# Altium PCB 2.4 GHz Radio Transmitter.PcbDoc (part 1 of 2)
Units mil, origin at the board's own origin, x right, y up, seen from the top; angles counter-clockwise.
Board outline 5905.26 x 4050.27 mil, 4 copper layers (Top Layer, GND, Power, Bottom Layer), stack 63.355 mil thick; 215 components, 108 nets, 659 pads, 107 vias.
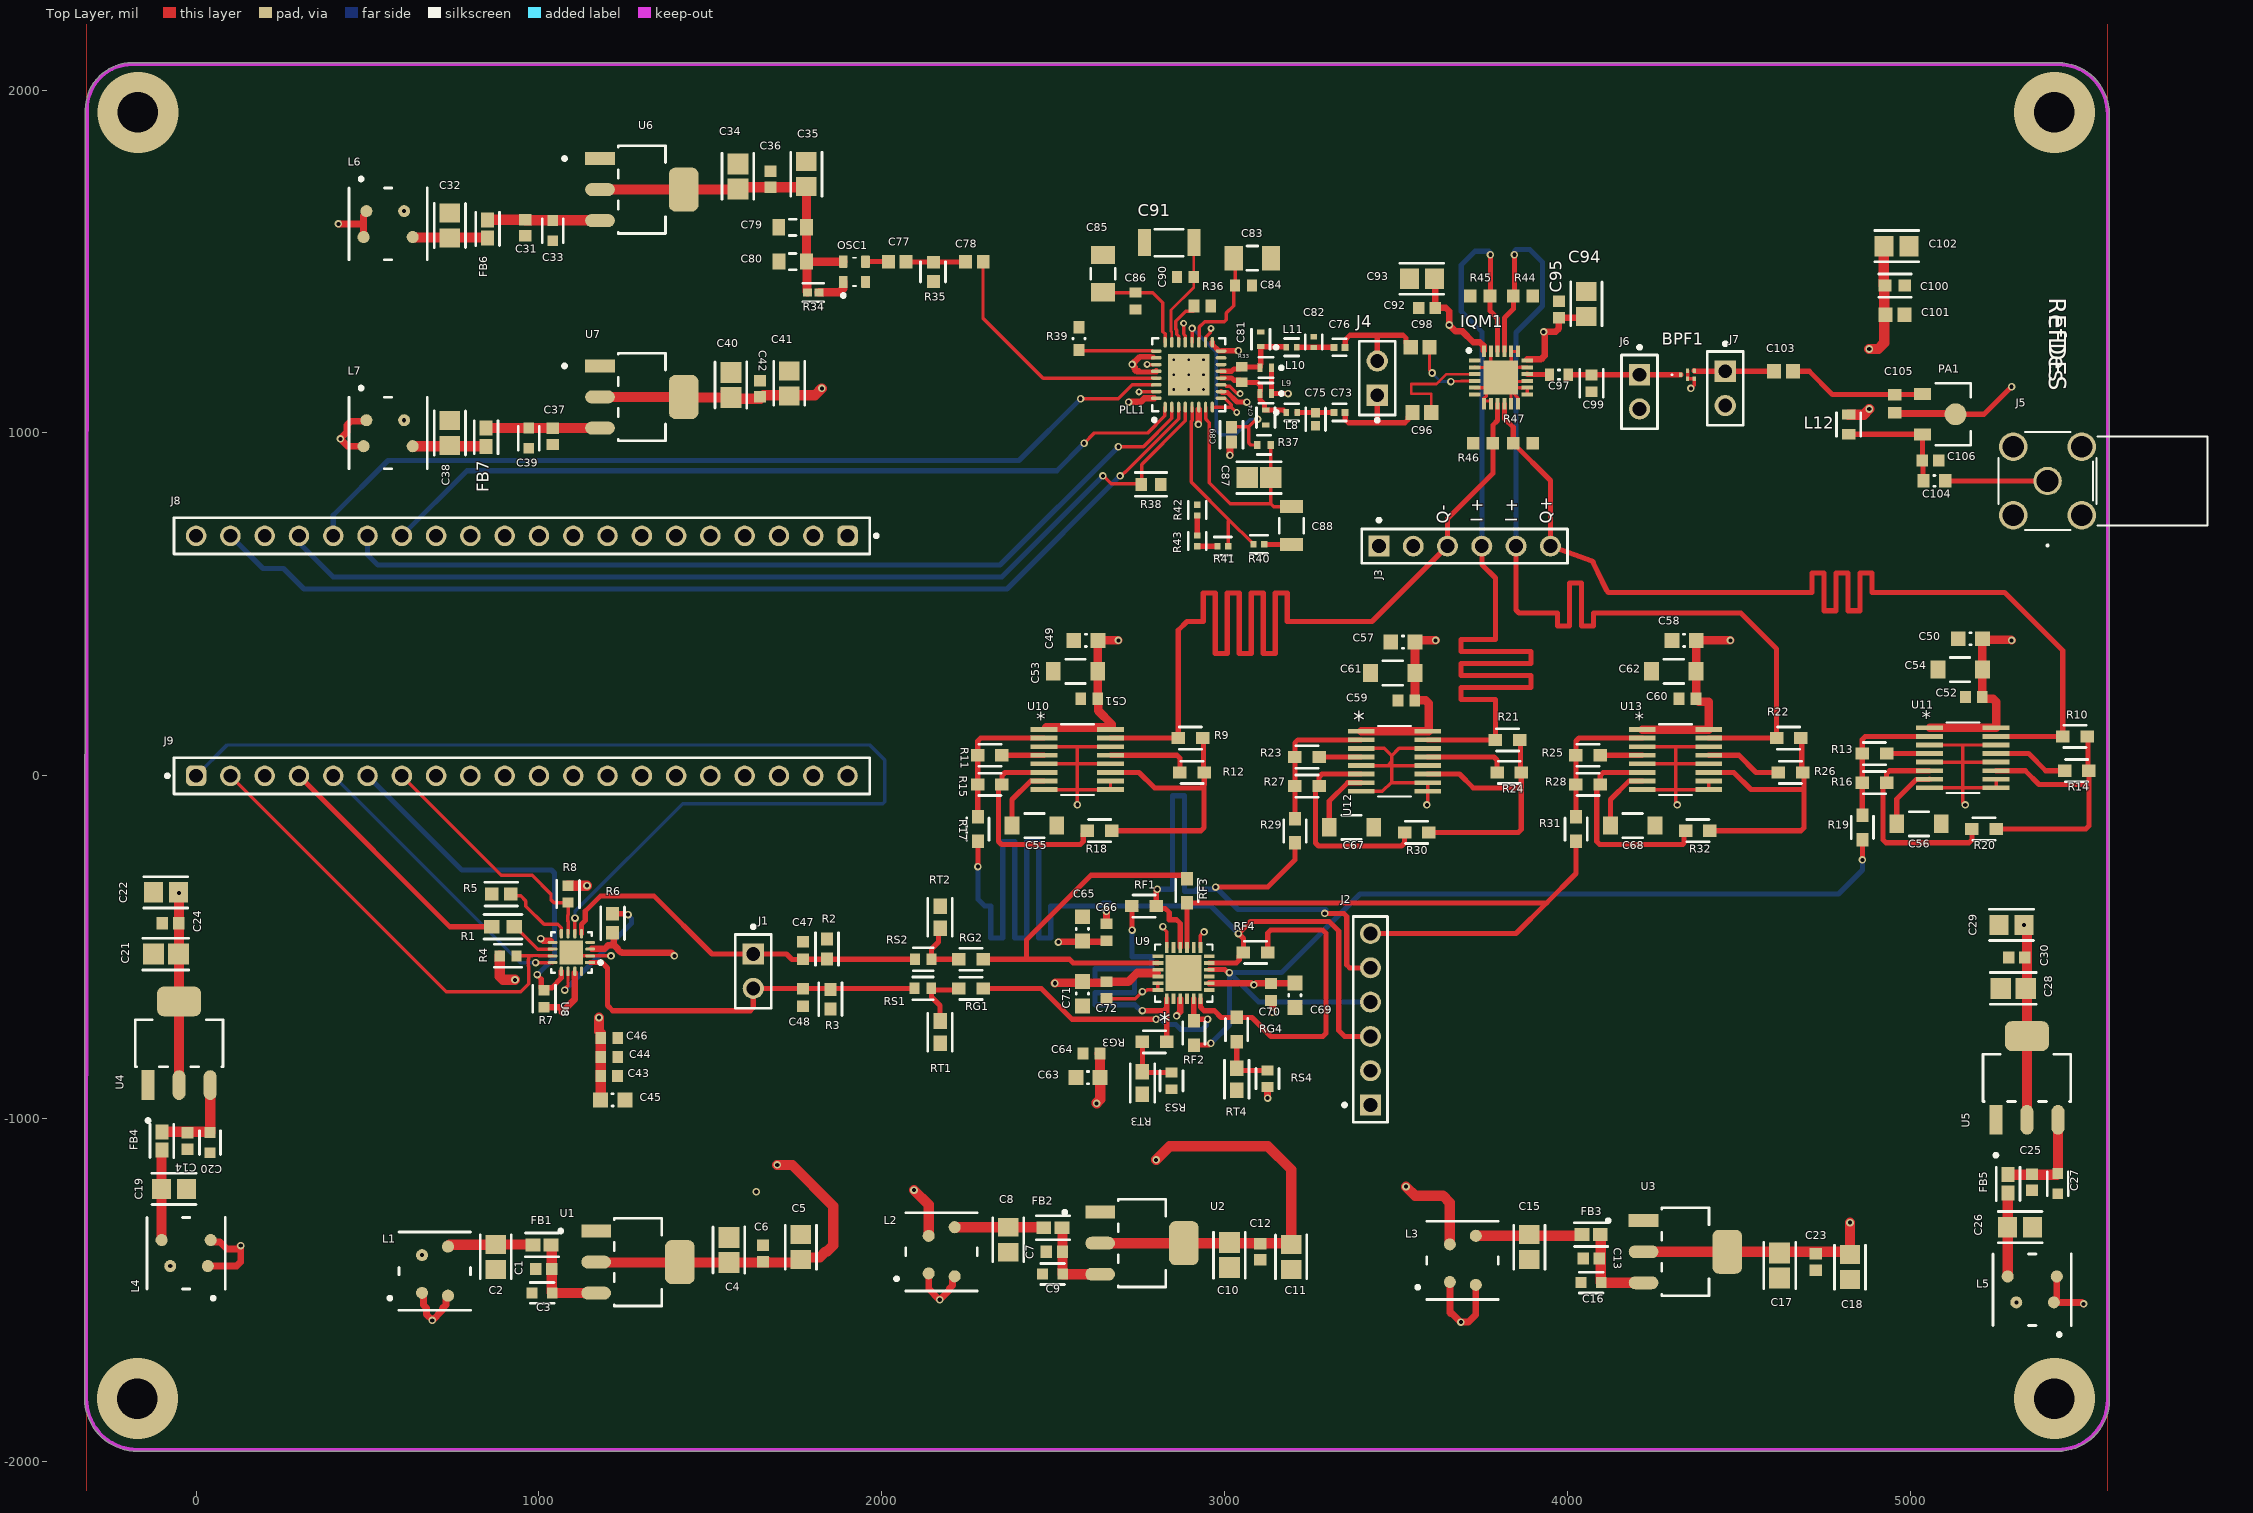
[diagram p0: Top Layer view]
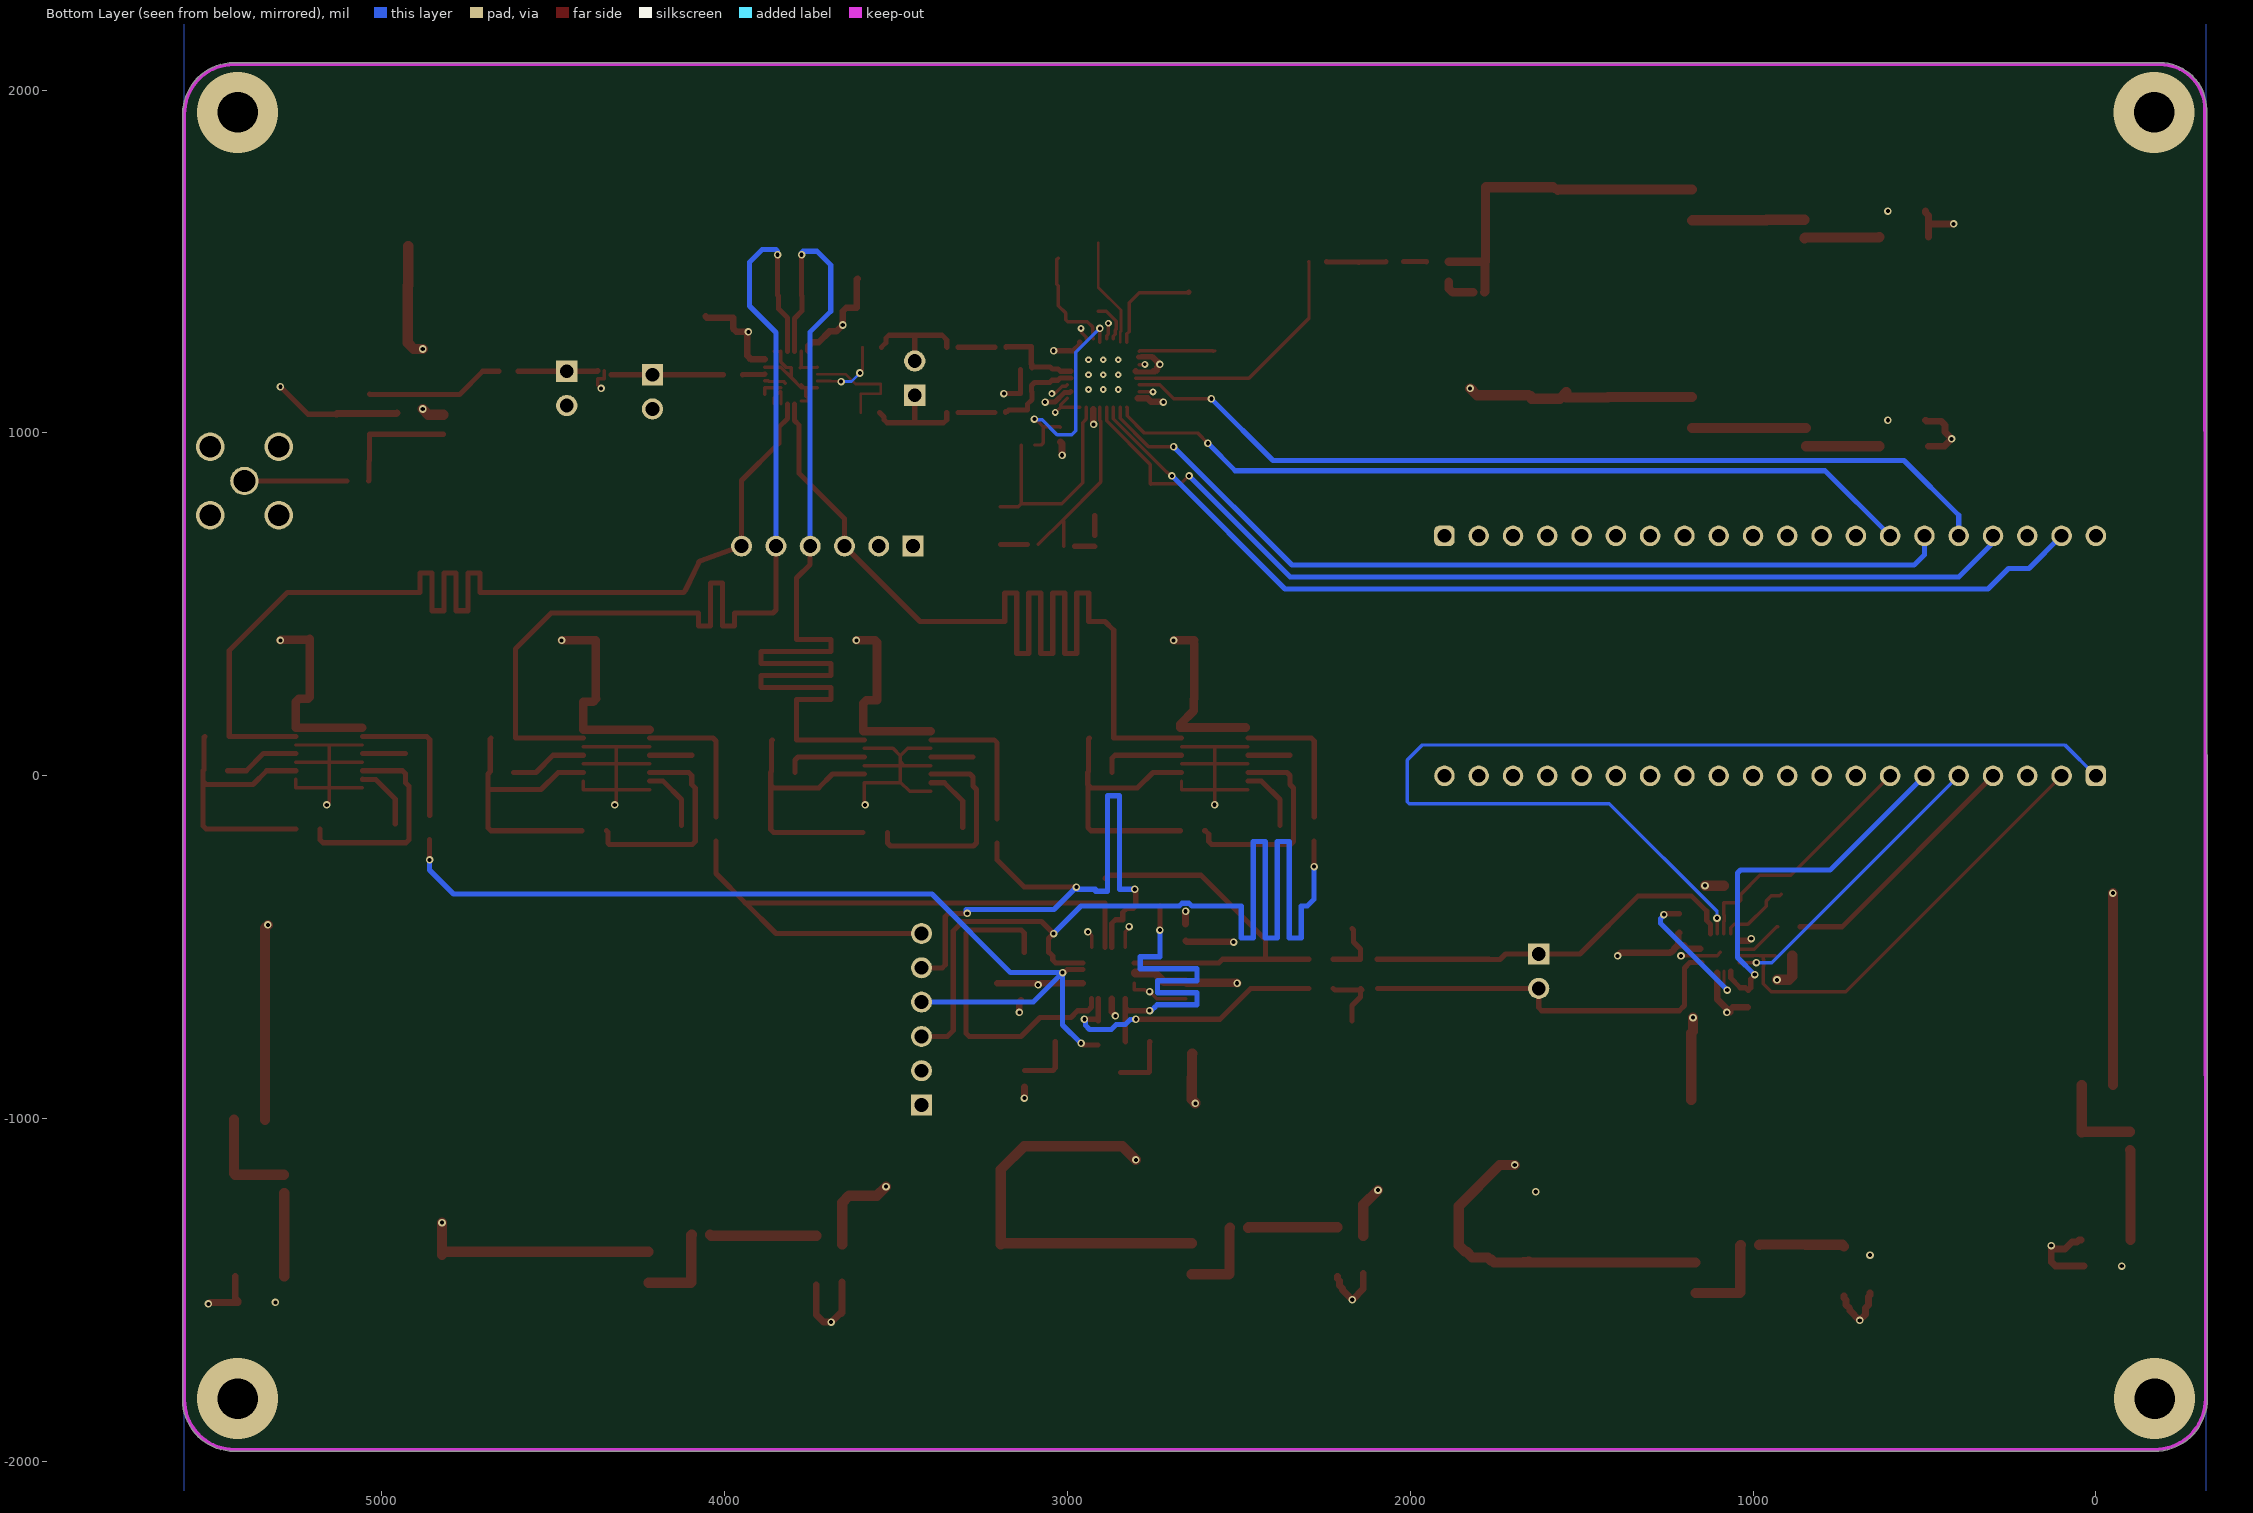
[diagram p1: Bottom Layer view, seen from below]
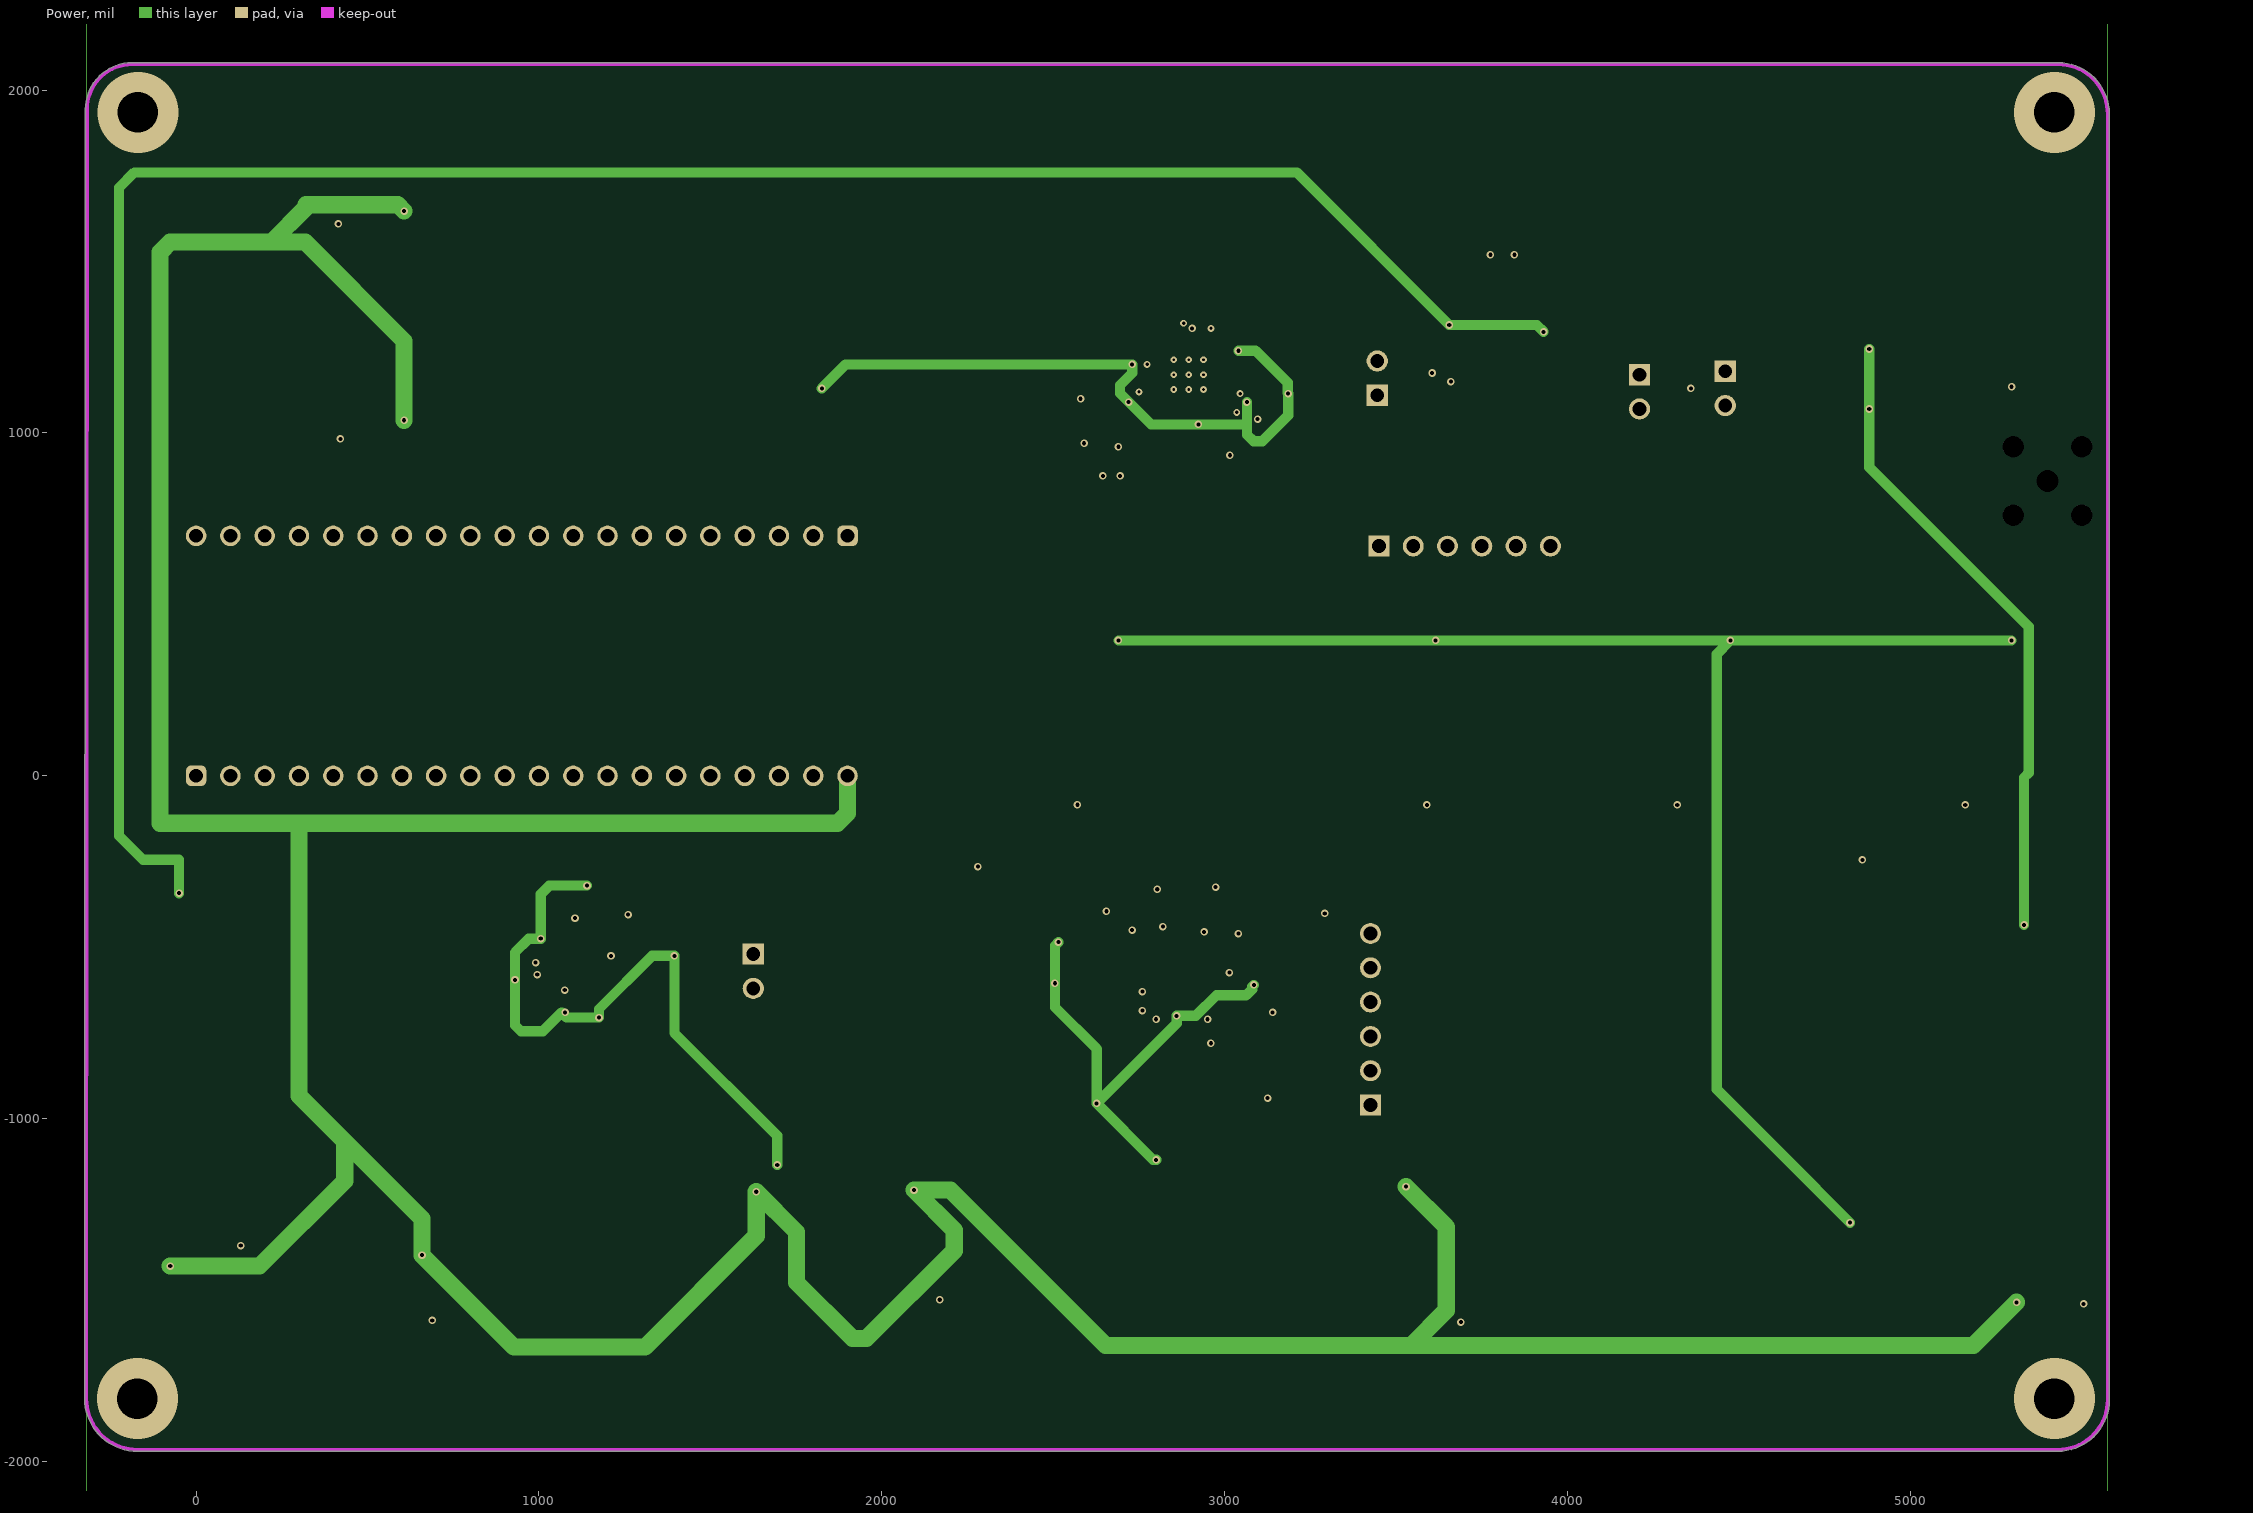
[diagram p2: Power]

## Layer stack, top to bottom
Top Solder: solder mask 1, Solder Resist, Dk 3.6
Top Layer: signal copper 1.378
Dielectric 1: prepreg 7.957, FR-4, Dk 3.61
GND: signal copper 1.378
Core: core 41.929, FR-4, Dk 4.4
Power: signal copper 1.378
Dielectric 2: prepreg 7.957, FR-4, Dk 3.61
Bottom Layer: signal copper 1.378
Bottom Solder: solder mask 1, Solder Resist, Dk 3.6

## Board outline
-325.02,-1816.32 -322.69,1944.12 cw(c-186.81,1944.11) -186.81,2080 5431.44,2080.02 5431.46,2080.01 cw(c5430.72,1930.72) 5580.02,1930.72 5580.04,1930 5580.25,-1819.6 cw(c5429.83,-1819.6) 5429.83,-1970.01 -171.08,-1970.26 cw(c-171.08,-1816.32)

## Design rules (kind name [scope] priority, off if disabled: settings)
AssemblyTestPointUsage [All] p0: scope1count=1 scope1_0_kind=Board scope1_0_value=Board scope2count=1 scope2_0_kind=Board scope2_0_value=Board commentlength=0
AssemblyTestpoint [All] p0: scope1count=1 scope1_0_kind=Board scope1_0_value=Board scope2count=1 scope2_0_kind=Board scope2_0_value=Board commentlength=0
BoardOutlineClearance [All] p0: scope1count=1 scope1_0_kind=Board scope1_0_value=Board scope2count=1 scope2_0_kind=Board scope2_0_value=Board commentlength=0 gap=15
BoardOutlineClearance [All] p1: gap=15 ignorepadtopadclearanceinfootprint=FALSE
Clearance [All] p0: scope1count=1 scope1_0_kind=Board scope1_0_value=Board scope2count=1 scope2_0_kind=Board scope2_0_value=Board commentlength=0 gap=5
Clearance "Clearance Polygons" [All] p0 off: scope1count=1 scope1_0_kind=Board scope1_0_value=Board scope2count=1 scope2_0_kind=Board scope2_0_value=Board commentlength=48 gap=10 // Protel DXP Scope 1 Expression Was: InPolygon
Clearance "Clearance Polygons" [InPolygon] p1: gap=10 ignorepadtopadclearanceinfootprint=FALSE
Clearance [All] p2: gap=5 ignorepadtopadclearanceinfootprint=FALSE
ComponentClearance [All] p0: scope1count=1 scope1_0_kind=Board scope1_0_value=Board scope2count=1 scope2_0_kind=Board scope2_0_value=Board commentlength=0 gap=1 collisioncheckmode=3
ComponentClearance "HM-TRP & UFL" [All] p0: scope1count=1 scope1_0_kind=Component scope1_0_value=X1 scope2count=1 scope2_0_kind=Component scope2_0_value=U1 commentlength=0 gap=0 collisioncheckmode=3
ComponentClearance "HM-TRP & UFL" [InComponent('X1') vs InComponent('U1')] p1: gap=0 collisioncheckmode=3 verticalgap=0 showdistances=FALSE
ComponentClearance [All] p2: gap=1 collisioncheckmode=3 verticalgap=1 showdistances=FALSE
DiffPairsRouting [All] p0: scope1count=1 scope1_0_kind=Board scope1_0_value=Board scope2count=1 scope2_0_kind=Board scope2_0_value=Board commentlength=0
DiffPairsRouting [All] p1: maxlimit=393.7 minlimit=5 mostfreqgap=8 toplayer_minwidth=5 toplayer_maxwidth=15 toplayer_prefwidth=8 midlayer1_minwidth=5 midlayer1_maxwidth=15 midlayer1_prefwidth=8 midlayer2_minwidth=5 midlayer2_maxwidth=15 midlayer2_prefwidth=8 bottomlayer_minwidth=5 bottomlayer_maxwidth=15 bottomlayer_prefwidth=8 maxuncoupledlength=500
FabricationTestPointUsage [All] p0: scope1count=1 scope1_0_kind=Board scope1_0_value=Board scope2count=1 scope2_0_kind=Board scope2_0_value=Board commentlength=0 valid=0 allowmultiple=FALSE
FabricationTestpoint [All] p0: scope1count=1 scope1_0_kind=Board scope1_0_value=Board scope2count=1 scope2_0_kind=Board scope2_0_value=Board commentlength=0 side=3 testpointundercomponent=TRUE minsize=40 maxsize=100 preferedsize=60 minholesize=0 maxholesize=40 preferedholesize=32 testpointgrid=1
FanoutControl Fanout_Default [All] p0: scope1count=1 scope1_0_kind=Board scope1_0_value=Board scope2count=1 scope2_0_kind=Board scope2_0_value=Board commentlength=30 // Fanout_Default (Default Rule)
FanoutControl Fanout_Small [All] p0 off: scope1count=1 scope1_0_kind=Board scope1_0_value=Board scope2count=1 scope2_0_kind=Board scope2_0_value=Board commentlength=84 // Protel DXP Scope 1 Expression Was: (CompPinCount < 5)   Fanout_Small (Default Rule)
FanoutControl Fanout_SOIC [All] p0 off: scope1count=1 scope1_0_kind=Board scope1_0_value=Board scope2count=1 scope2_0_kind=Board scope2_0_value=Board commentlength=71 // Protel DXP Scope 1 Expression Was: IsSOIC   Fanout_SOIC (Default Rule)
FanoutControl Fanout_LCC [All] p0 off: scope1count=1 scope1_0_kind=Board scope1_0_value=Board scope2count=1 scope2_0_kind=Board scope2_0_value=Board commentlength=69 // Protel DXP Scope 1 Expression Was: IsLCC   Fanout_LCC (Default Rule)
FanoutControl Fanout_BGA [All] p0 off: scope1count=1 scope1_0_kind=Board scope1_0_value=Board scope2count=1 scope2_0_kind=Board scope2_0_value=Board commentlength=69 // Protel DXP Scope 1 Expression Was: IsBGA   Fanout_BGA (Default Rule)
Height [All] p0: scope1count=1 scope1_0_kind=Board scope1_0_value=Board scope2count=1 scope2_0_kind=Board scope2_0_value=Board commentlength=0
HoleSize [All] p0: scope1count=1 scope1_0_kind=Board scope1_0_value=Board scope2count=1 scope2_0_kind=Board scope2_0_value=Board commentlength=0 absolutevalues=TRUE maxlimit=265 minlimit=10 maxpercent=80.000 minpercent=20.000
HoleSize [All] p1: absolutevalues=TRUE maxlimit=265 minlimit=10 maxpercent=80.000 minpercent=20.000
HoleToHoleClearance [All] p0: scope1count=1 scope1_0_kind=Board scope1_0_value=Board scope2count=1 scope2_0_kind=Board scope2_0_value=Board commentlength=0
HoleToHoleClearance [All] p1: gap=10 allowstackedmicrovias=FALSE
LayerPairs [All] p0: scope1count=1 scope1_0_kind=Board scope1_0_value=Board scope2count=1 scope2_0_kind=Board scope2_0_value=Board commentlength=0 enforce=TRUE
MinimumAnnularRing [All] p0: scope1count=1 scope1_0_kind=Board scope1_0_value=Board scope2count=1 scope2_0_kind=Board scope2_0_value=Board commentlength=0 minimumring=4
MinimumAnnularRing [All] p1: minimumring=4
MinimumSolderMaskSliver [All] p0: scope1count=1 scope1_0_kind=Board scope1_0_value=Board scope2count=1 scope2_0_kind=Board scope2_0_value=Board commentlength=0
MinimumSolderMaskSliver [All] p1: minsoldermaskwidth=0
NetAntennae [All] p0: scope1count=1 scope1_0_kind=Board scope1_0_value=Board scope2count=1 scope2_0_kind=Board scope2_0_value=Board commentlength=0
PasteMaskExpansion [All] p0: scope1count=1 scope1_0_kind=Board scope1_0_value=Board scope2count=1 scope2_0_kind=Board scope2_0_value=Board commentlength=0 expansion=0
PlaneClearance [All] p0: scope1count=1 scope1_0_kind=Board scope1_0_value=Board scope2count=1 scope2_0_kind=Board scope2_0_value=Board commentlength=0 clearance=10
PlaneClearance [All] p1: clearance=10
PlaneConnect [All] p0: scope1count=1 scope1_0_kind=Board scope1_0_value=Board scope2count=1 scope2_0_kind=Board scope2_0_value=Board commentlength=0 planeconnectstyle=Relief reliefexpansion=4 reliefentries=4 reliefconductorwidth=6 reliefairgap=6
PlaneConnect [All] p1: planeconnectstyle=Relief reliefexpansion=4 reliefentries=4 reliefconductorwidth=6 reliefairgap=6
PolygonConnect [All] p0: scope1count=1 scope1_0_kind=Board scope1_0_value=Board scope2count=1 scope2_0_kind=Board scope2_0_value=Board commentlength=0 connectstyle=Relief reliefconductorwidth=10 reliefentries=4 polygonreliefangle="90 Angle"
PolygonConnect "Via connect style" [All] p0 off: scope1count=1 scope1_0_kind=Board scope1_0_value=Board scope2count=1 scope2_0_kind=Board scope2_0_value=Board commentlength=44 connectstyle=Direct reliefconductorwidth=10 reliefentries=4 polygonreliefangle="90 Angle" // Protel DXP Scope 1 Expression Was: isVia
PolygonConnect "Via connect style" [isVia] p1: connectstyle=Direct reliefconductorwidth=10 reliefentries=4 polygonreliefangle="90 Angle" airgapwidth=10
PolygonConnect [All] p2: connectstyle=Relief reliefconductorwidth=10 reliefentries=4 polygonreliefangle="90 Angle" airgapwidth=6
RoutingCorners [All] p0: scope1count=1 scope1_0_kind=Board scope1_0_value=Board scope2count=1 scope2_0_kind=Board scope2_0_value=Board commentlength=0 cornerstyle=45-Degree minsetback=49.21 maxsetback=49.21
RoutingCorners [All] p1: cornerstyle=45-Degree minsetback=49.21 maxsetback=49.21
RoutingLayers [All] p0: scope1count=1 scope1_0_kind=Board scope1_0_value=Board scope2count=1 scope2_0_kind=Board scope2_0_value=Board commentlength=0 top layer=Automatic mid layer 1=Automatic mid layer 2=Automatic bottom layer=Automatic
RoutingPriority [All] p0: scope1count=1 scope1_0_kind=Board scope1_0_value=Board scope2count=1 scope2_0_kind=Board scope2_0_value=Board commentlength=0
RoutingTopology [All] p0: scope1count=1 scope1_0_kind=Board scope1_0_value=Board scope2count=1 scope2_0_kind=Board scope2_0_value=Board commentlength=0 topology=Shortest
RoutingVias [All] p0: scope1count=1 scope1_0_kind=Board scope1_0_value=Board scope2count=1 scope2_0_kind=Board scope2_0_value=Board commentlength=0 holewidth=12 width=22 viastyle="Through Hole" minholewidth=10 minwidth=18 maxholewidth=100 maxwidth=114
RoutingVias [All] p1: holewidth=12 width=22 viastyle="Through Hole" minholewidth=10 minwidth=18 maxholewidth=100 maxwidth=114
ShortCircuit [All] p0: scope1count=1 scope1_0_kind=Board scope1_0_value=Board scope2count=1 scope2_0_kind=Board scope2_0_value=Board commentlength=0 allowed=FALSE
SilkToBoardRegionClearance [All] p0: scope1count=1 scope1_0_kind=Board scope1_0_value=Board scope2count=1 scope2_0_kind=Board scope2_0_value=Board commentlength=0
SilkToSilkClearance [All] p0: scope1count=1 scope1_0_kind=Board scope1_0_value=Board scope2count=1 scope2_0_kind=Board scope2_0_value=Board commentlength=0
SilkToSilkClearance [All] p1: silktosilkclearance=0
SilkToSolderMaskClearance [All] p0 off: scope1count=1 scope1_0_kind=Board scope1_0_value=Board scope2count=1 scope2_0_kind=Board scope2_0_value=Board commentlength=44 // Protel DXP Scope 1 Expression Was: IsPad
SilkToSolderMaskClearance [IsPad] p1: minsilkscreentomaskgap=5 clearancetoexposedcopper=TRUE
SolderMaskExpansion [All] p0: scope1count=1 scope1_0_kind=Board scope1_0_value=Board scope2count=1 scope2_0_kind=Board scope2_0_value=Board commentlength=0 expansion=2.5
SolderMaskExpansion [All] p1: expansion=2.5 istentingtop=FALSE
UnRoutedNet [All] p0: scope1count=1 scope1_0_kind=Board scope1_0_value=Board scope2count=1 scope2_0_kind=Board scope2_0_value=Board commentlength=0
UnpouredPolygon [All] p0: scope1count=1 scope1_0_kind=Board scope1_0_value=Board scope2count=1 scope2_0_kind=Board scope2_0_value=Board commentlength=0
Width [All] p0: scope1count=1 scope1_0_kind=Board scope1_0_value=Board scope2count=1 scope2_0_kind=Board scope2_0_value=Board commentlength=0 maxlimit=400 minlimit=6 preferedwidth=8
Width 3V3 [All] p0: scope1count=1 scope1_0_kind=NetClass scope1_0_value=3V3 scope2count=1 scope2_0_kind=Board scope2_0_value=Board commentlength=0 maxlimit=30 minlimit=10 preferedwidth=20
Width Power [All] p0: scope1count=1 scope1_0_kind=NetClass scope1_0_value=Power scope2count=1 scope2_0_kind=Board scope2_0_value=Board commentlength=0 maxlimit=40 minlimit=20 preferedwidth=30
Width GND [All] p0: scope1count=1 scope1_0_kind=Net scope1_0_value=GND scope2count=1 scope2_0_kind=Board scope2_0_value=Board commentlength=0 maxlimit=30 minlimit=10 preferedwidth=20
Width GND [InNet('GND')] p1: maxlimit=30 minlimit=10 preferedwidth=20
Width Power [InNetClass('Power')] p2: maxlimit=40 minlimit=20 preferedwidth=30
Width 3V3 [InNetClass('3V3')] p3: maxlimit=30 minlimit=10 preferedwidth=20
Width [All] p4: maxlimit=400 minlimit=6 preferedwidth=8
20 further rules are at their usual default settings.

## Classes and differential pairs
component class RF_FrontEnd: BPF1 C92 C93 C94 C95 C96 C97 C98 C99 C100 C101 C102 C103 C104 C105 C106 IQM1 J5 J6 J7 L12 PA1 R44 R45 R46 R47
component class PowerFilterLDO: C1 C2 C3 C4 C5 C6 C7 C8 C9 C10 C11 C12 C13 C14 C15 C16 C17 C18 C19 C20 C21 C22 C23 C24 C25 C26 C27 C28 C29 C30 C31 C32 C33 C34 C35 C36 C37 C38 C39 C40 C41 C42 FB1 FB2 FB3 FB4 FB5 FB6 FB7 L1 L2 L3 L4 L5 L6 L7 U1 U2 U3 U4 U5 U6 U7
component class FrequencySynthesis: C73 C74 C75 C76 C77 C78 C79 C80 C81 C82 C83 C84 C85 C86 C87 C88 C89 C90 C91 J4 L8 L9 L10 L11 OSC1 PLL1 R33 R34 R35 R36 R37 R38 R39 R40 R41 R42 R43
component class DSP: J8 J9
component class AnalogBaseband: C43 C44 C45 C46 C47 C48 C49 C50 C51 C52 C53 C54 C55 C56 C57 C58 C59 C60 C61 C62 C63 C64 C65 C66 C67 C68 C69 C70 C71 C72 J1 J2 J3 R1 R2 R3 R4 R5 R6 R7 R8 R9 R10 R11 R12 R13 R14 R15 R16 R17 R18 R19 R20 R21 R22 R23 R24 R25 R26 R27 R28 R29 R30 R31 R32 RF1 RF2 RF3 RF4 RG1 RG2 RG3 RG4 RS1 RS2 RS3 RS4 RT1 RT2 RT3 RT4 U8 U9 U10 U11 U12 U13
differential pair QOUT: +QOUT_P -QOUT_N
differential pair QIN: +QIN_P -QIN_N
differential pair LO3: +LO3_P -LO3_N
differential pair LO2: +LO2_P -LO2_N
differential pair IOUT: +IOUT_P -IOUT_N
differential pair IN2: +IN2_P -IN2_N
differential pair IN1: +IN1_P -IN1_N
differential pair LO: +LO_P -LO_N
differential pair LO1: +LO1_P -LO1_N
differential pair BBQ: +BBQ_P -BBQ_N
differential pair " ": +BBI_P -BBI_N

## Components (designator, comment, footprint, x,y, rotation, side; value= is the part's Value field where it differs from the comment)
BPF1 "DEA142450BT-3028A1" DEA142450BT3028A1 4350,1170 r0 top
C1 "0.1 uF" CAPC1608X95X40LL15T15 1013.82,-1438.13 r0 top
C2 "10 uF" FP-GCM21B-0_15-IPC_A 873.82,-1403.13 r270 top
C3 "1 uF" FP-VJ0603Y105KXJCW1BC-MFG 1009.29,-1508.13 r180 top
C4 "4.7 uF" FP-GCJ21B-0_3-IPC_A 1553.82,-1383.13 r90 top
C5 "10 uF" FP-GCM21B-0_15-IPC_A 1763.82,-1374.59 r90 top
C6 "0.1 uF" CAPC1608X95X40LL15T15 1653.82,-1393.13 r270 top
C7 "0.1 uF" CAPC1608X95X40LL15T15 2503.35,-1388.13 r0 top
C8 "10 uF" FP-GCM21B-0_15-IPC_A 2368.82,-1353.13 r270 top
C9 "1 uF" FP-VJ0603Y105KXJCW1BC-MFG 2498.35,-1453.13 r180 top
C10 "4.7 uF" FP-GCJ21B-0_3-IPC_A 3013.82,-1398.13 r270 top
C11 "10 uF" FP-GCM21B-0_15-IPC_A 3193.82,-1403.13 r270 top
C12 "0.1 uF" CAPC1608X95X40LL15T15 3103.82,-1388.13 r90 top
C13 "0.1 uF" CAPC1608X95X40LL15T15 4068.82,-1408.13 r0 top
C14 "0.1 uF" CAPC1608X95X40LL15T15 -24.69,-1065 r90 top
C15 "10 uF" FP-GCM21B-0_15-IPC_A 3888.82,-1374.59 r270 top
C16 "1 uF" FP-VJ0603Y105KXJCW1BC-MFG 4068.82,-1478.13 r180 top
C17 "4.7 uF" FP-GCJ21B-0_3-IPC_A 4618.82,-1428.13 r270 top
C18 "10 uF" FP-GCM21B-0_15-IPC_A 4823.82,-1433.13 r270 top
C19 "10 uF" FP-GCM21B-0_15-IPC_A -64.69,-1205 r0 top
C20 "1 uF" FP-VJ0603Y105KXJCW1BC-MFG 40.31,-1070 r270 top
C21 "4.7 uF" FP-GCJ21B-0_3-IPC_A -88.25,-520 r180 top
C22 "10 uF" FP-GCM21B-0_15-IPC_A -88.22,-340 r180 top
C23 "0.1 uF" CAPC1608X95X40LL15T15 4723.82,-1418.13 r90 top
C24 "0.1 uF" CAPC1608X95X40LL15T15 -74.69,-430 r0 top
C25 "0.1 uF" CAPC1608X95X40LL15T15 5355,-1185 r90 top
C26 "10 uF" FP-GCM21B-0_15-IPC_A 5320,-1316.17 r0 top
C27 "1 uF" FP-VJ0603Y105KXJCW1BC-MFG 5430,-1189.53 r270 top
C28 "4.7 uF" FP-GCJ21B-0_3-IPC_A 5300,-620 r180 top
C29 "10 uF" FP-GCM21B-0_15-IPC_A 5295,-435 r180 top
C30 "0.1 uF" CAPC1608X95X40LL15T15 5310,-530 r0 top
C31 "0.1 uF" CAPC1608X95X40LL15T15 960,1598.62 r90 top
C32 "10 uF" FP-GCM21B-0_15-IPC_A 740,1605 r90 top
C33 "1 uF" FP-VJ0603Y105KXJCW1BC-MFG 1040,1590 r270 top
C34 "4.7 uF" FP-GCJ21B-0_3-IPC_A 1580,1748.57 r90 top
C35 "10 uF" FP-GCM21B-0_15-IPC_A 1780,1755 r90 top
C36 "0.1 uF" CAPC1608X95X40LL15T15 1675,1740 r270 top
C37 "0.1 uF" CAPC1608X95X40LL15T15 1040,990 r90 top
C38 "10 uF" FP-GCM21B-0_15-IPC_A 740,1000 r90 top
C39 "1 uF" FP-VJ0603Y105KXJCW1BC-MFG 970,985 r270 top
C40 "4.7 uF" FP-GCJ21B-0_3-IPC_A 1560,1140 r90 top
C41 "10 uF" FP-GCM21B-0_15-IPC_A 1730,1145 r90 top
C42 "0.1 uF" CAPC1608X95X40LL15T15 1645,1128.62 r270 top
C43 "0.1uF" CAPC1608X87X35LL15T15 1204.61,-875 r180 top
C44 "0.1uF" CAPC1608X87X35LL15T15 1205,-820 r180 top
C45 "10uF" CAPC0603(1608)100_M 1215,-945 r180 top
C46 "0.1uF" CAPC1608X87X35LL15T15 1205,-765 r180 top
C47 "" CAPC1608X90X35LL15T15 1770,-510 r270 top
C48 "" CAPC1608X90X35LL15T15 1770,-646.38 r90 top
C49 "10uF" CAPC0603(1608)100_M 2595,395 r0 top
C50 "10uF" CAPC0603(1608)100_M 5175,400 r0 top
C51 "0.1uF" CAPC1608X87X35LL15T15 2605,225 r0 top
C52 "0.1uF" CAPC1608X87X35LL15T15 5185,230 r0 top
C53 "CGA5L2C0G1H104J160AA" FP-CGA5L-MFG 2565,305 r180 top
C54 "CGA5L2C0G1H104J160AA" FP-CGA5L-MFG 5145,310 r180 top
C55 "CGA5L2C0G1H104J160AA" FP-CGA5L-MFG 2445,-145 r0 top
C56 "CGA5L2C0G1H104J160AA" FP-CGA5L-MFG 5025,-140 r0 top
C57 "10uF" CAPC0603(1608)100_M 3520,390 r0 top
C58 "10uF" CAPC0603(1608)100_M 4340,395 r0 top
C59 "0.1uF" CAPC1608X87X35LL15T15 3530,220 r0 top
C60 "0.1uF" CAPC1608X87X35LL15T15 4350,225 r0 top
C61 "CGA5L2C0G1H104J160AA" FP-CGA5L-MFG 3490,300 r180 top
C62 "CGA5L2C0G1H104J160AA" FP-CGA5L-MFG 4310,305 r180 top
C63 "10uF" CAPC0603(1608)100_M 2601.3,-880 r0 top
C64 "0.1uF" CAPC1608X87X35LL15T15 2611.3,-810 r0 top
C65 "10uF" CAPC0603(1608)100_M 2585,-446.3 r270 top
C66 "0.1uF" CAPC1608X87X35LL15T15 2655,-456.3 r270 top
C67 "CGA5L2C0G1H104J160AA" FP-CGA5L-MFG 3370,-150 r0 top
C68 "CGA5L2C0G1H104J160AA" FP-CGA5L-MFG 4190,-145 r0 top
C69 "10uF" CAPC0603(1608)100_M 3205,-640 r90 top
C70 "0.1uF" CAPC1608X87X35LL15T15 3135,-630.39 r90 top
C71 "10uF" CAPC0603(1608)100_M 2585,-635.43 r90 top
C72 "0.1uF" CAPC1608X87X35LL15T15 2655,-625 r90 top
C73 "1nF" FP-C0402C102K4RAC7411-MFG 3335,1060 r0 top
C74 "2.2pF" FP-CGA2B-IPC_B 3120,1045 r270 top
C75 "1.5pF" FP-GCM155-0_05-IPC_A 3265,1040 r270 top
C76 "1nF" FP-C0402C102K4RAC7411-MFG 3335,1250 r0 top
C77 "1nF" CAPC1608X95X40NL15T15 2045,1500 r0 top
C78 "1nF" CAPC1608X95X40NL15T15 2270,1500 r0 top
C79 "1nF" FP-CGA3E-0_3-0_1-IPC_A 1739.65,1600 r180 top
C80 "1nF" FP-CGA3E-0_3-0_1-IPC_A 1740,1500 r180 top
C81 "2.2pF" FP-CGA2B-IPC_B 3105,1273.35 r90 top
C82 "1.5pF" FP-CGA2B-MFG 3260,1265 r90 top
C83 "100nF" FP-GRM31C-0_2-e0_3_0_8-IPC_B 3080.84,1510 r0 top
C84 "10pF" CAPC1608X92X38LL15T08 3055,1430 r180 top
C85 "100nF" FP-GRM31C-0_2-e0_3_0_8-IPC_B 2645,1465 r90 top
C86 "10pF" CAPC1608X92X38LL15T08 2740,1385 r90 top
C87 "2.7nF" FP-C2012-125-0_2-IPC_A 3100,870 r180 top
C88 "39nF" FP-C1206C-EB-MFG 3195,730 r270 top
C89 "1.2nF" FP-C1608-080-0_1-IPC_C 3020,995 r270 top
C90 "10pF" CAPC1608X92X38LL15T08 2885,1455 r0 top
C91 "100nF" FP-CGA5L-0_3-0_1-IPC_A 2838.15,1555 r180 top
C92 "0.1 uF" CAPC1608X95X40LL15T15 3590,1365 r0 top
C93 "10 uF" FP-GCM21B-0_15-IPC_A 3575,1450 r180 top
C94 "10 uF" FP-GCM21B-0_15-IPC_A 4055,1376.47 r270 top
C95 "0.1 uF" CAPC1608X95X40LL15T15 3975,1360 r270 top
C96 "12 pF" CAPC1608X95X40ML15T15 3575,1060 r0 top
C97 "6.8 pF" CAPC0603(1608)100_L 3975,1170 r0 top
C98 "12 pF" CAPC1608X95X40ML15T15 3570,1250 r0 top
C99 "0.2 pF" FP-GQM187-0_15-IPC_C 4070,1145 r270 top
C100 "10 nF" FP-GRM188-0_1-e0_2_0_5-IPC_B 4955,1430 r0 top
C101 "12 pF" CAPC1608X95X40ML15T15 4955,1345 r180 top
C102 "10 uF" FP-GCM21B-0_15-IPC_A 4960,1545 r0 top
C103 "12 pF" CAPC1608X95X40ML15T15 4630,1180 r0 top
C104 "2.2 pF" CAPC0603(1608)100_N 5070,860 r0 top
C105 "1.2 pF" CAPC1608X92X38NL15T08 4955,1085 r90 top
C106 "1 pF" CAPC1608X95X40LL15T15 5058.5,920 r180 top
FB1 "" FP-BLM18-0_15-t0_8-IPC_B 1008.82,-1368.13 r0 top
FB2 "" FP-BLM18-0_15-t0_8-IPC_B 2498.82,-1318.13 r0 top
FB3 "" FP-BLM18-0_15-t0_8-IPC_B 4068.82,-1338.13 r0 top
FB4 "" FP-BLM18-0_15-t0_8-IPC_B -99.69,-1065 r90 top
FB5 "" FP-BLM18-0_15-t0_8-IPC_B 5285,-1190 r90 top
FB6 "" FP-BLM18-0_15-t0_8-IPC_B 850,1595 r90 top
FB7 "" FP-BLM18-0_15-t0_8-IPC_B 845.59,987.72 r90 top
IQM1 "TRF3705IRGET" QFN50P400X400X100-25N-D 3805.79,1161.77 r0 top
J1 "TSW-102-07-G-S" FP-TSW-102-07-G-S-MFG 1625,-570 r270 top
J2 "TSW-106-07-S-S" SMTC-TSW-106-07-S-S_V 3425,-710 r90 top
J3 "TSW-106-07-S-S" SMTC-TSW-106-07-S-S_V 3700,670 r0 top
J4 "TSW-102-07-L-S" FP-TSW-102-07-L-S-MFG 3445,1160 r90 top
J5 "SMA-J-P-H-RA-TH1" CONN_SMA-J-P-H-RA-TH1_SAI 5400,860 r270 top
J6 "TSW-102-07-G-S" FP-TSW-102-07-G-S-MFG 4210,1120 r270 top
J7 "TSW-102-07-G-S" FP-TSW-102-07-G-S-MFG 4460,1130 r270 top
J8 "61302011821" 61302011821 950,700 r180 top
J9 "61302011821" 61302011821 950,0 r0 top
L1 "" FP-DLW5BS-MFG 695.98,-1444.63 r0 top
L2 "" FP-DLW5BS-MFG 2173.82,-1388.13 r0 top
L3 "" FP-DLW5BS-MFG 3693.82,-1413.13 r0 top
L4 "" FP-DLW5BS-MFG -29.1,-1392.6 r90 top
L5 "" FP-DLW5BS-MFG 5355.33,-1498.77 r90 top
L6 "" FP-DLW5BS-MFG 560,1610 r270 top
L7 "" FP-DLW5BS-MFG 560,1000 r270 top
L8 "3.6nH" FP-LQG15HH_02-MFG 3195.75,1060 r0 top
L9 "7.5nH" FP-LQG15WH_02-MFG 3120,1115 r180 top
L10 "7.5nH" FP-LQG15WH_02-MFG 3120,1190 r180 top
L11 "3.6nH" FP-LQG15HH_02-MFG 3195,1250 r0 top
L12 "15 nH" FP-LQW18CA_00-MFG 4820,1025 r90 top
OSC1 "LMK6CE10000DDLFT" DLF0004A_MFG 1920,1470 r90 top
PA1 "ADL5320ARKZ-R7" FP-RK-3-MFG 5125.26,1054.57 r270 top
PLL1 "ADF4350BCPZ-RL7" ADI-CP-32-2_L 2895,1170 r90 top
R1 "CRGCQ0603F22R" FP-CRGCQ0603-IPC_A 895,-440 r0 top
R2 "" FP-CR0603-IPC_B 1840,-505 r270 top
R3 "" FP-CR0603-IPC_B 1850,-651.38 r90 top
R4 "10K" FP-CRGCQ0603-IPC_C 910,-525 r0 top
R5 "0" FP-RMCF0603-IPC_B 890,-345 r0 top
R6 "0" FP-RMCF0603-IPC_B 1215,-430 r90 top
R7 "10K" FP-CRGCQ0603-IPC_C 1015,-650 r270 top
R8 "10K" FP-CRGCQ0603-IPC_C 1085,-345 r270 top
R9 "CPF0603B120KE1" FP-CPF0603-MFG 2900,110 r0 top
R10 "CPF0603B120KE1" FP-CPF0603-MFG 5480,115 r0 top
R11 "CPF0603B120KE1" FP-CPF0603-MFG 2315,60 r0 top
R12 "CPF0603B120KE1" FP-CPF0603-MFG 2905,10 r0 top
R13 "CPF0603B120KE1" FP-CPF0603-MFG 4895,65 r0 top
R14 "CPF0603B120KE1" FP-CPF0603-MFG 5485,15 r0 top
R15 "CPF0603B120KE1" FP-CPF0603-MFG 2315,-25 r0 top
R16 "CPF0603B120KE1" FP-CPF0603-MFG 4895,-20 r0 top
R17 "CPF0603B120KE1" FP-CPF0603-MFG 2280,-155.43 r90 top
R18 "CPF0603B120KE1" FP-CPF0603-MFG 2635,-160 r0 top
R19 "CPF0603B120KE1" FP-CPF0603-MFG 4860,-150.43 r90 top
R20 "CPF0603B120KE1" FP-CPF0603-MFG 5215,-155 r0 top
R21 "CPF0603B120KE1" FP-CPF0603-MFG 3825,105 r0 top
R22 "CPF0603B120KE1" FP-CPF0603-MFG 4645,110 r0 top
R23 "CPF0603B120KE1" FP-CPF0603-MFG 3240,55 r0 top
R24 "CPF0603B120KE1" FP-CPF0603-MFG 3830,10 r0 top
R25 "CPF0603B120KE1" FP-CPF0603-MFG 4060,60 r0 top
R26 "CPF0603B120KE1" FP-CPF0603-MFG 4650,10 r0 top
R27 "CPF0603B120KE1" FP-CPF0603-MFG 3240,-30 r0 top
R28 "CPF0603B120KE1" FP-CPF0603-MFG 4060,-25 r0 top
R29 "CPF0603B120KE1" FP-CPF0603-MFG 3205,-160.43 r90 top
R30 "CPF0603B120KE1" FP-CPF0603-MFG 3560,-165 r0 top
R31 "CPF0603B120KE1" FP-CPF0603-MFG 4025,-155.43 r90 top
R32 "CPF0603B120KE1" FP-CPF0603-MFG 4380,-160 r0 top
R33 "100" RESC1609X50X30LL10T20 3050,1170 r270 top
R34 "10k" FP-CRG0402-IPC_B 1800,1410 r0 top
R35 "51" FP-CRCW0603-e3-IPC_B 2150,1470 r270 top
R36 "4.7k" RESC1609X50X30NL10T20 2935,1370 r0 top
R37 "680" FP-RT0402-MFG 3115,965 r180 top
R38 "10k" FP-MCT0603-IPC_B 2785,850 r0 top
R39 "100" FP-SR0603-MFG 2575,1275 r90 top
R40 "360" FP-CRCW0402-e3-IPC_C 3100,675 r180 top
R41 "360" FP-CRCW0402-e3-IPC_C 2995,670 r180 top
R42 "360" FP-CRCW0402-e3-IPC_C 2920,775 r90 top
R43 "360" FP-CRCW0402-e3-IPC_C 2920,685 r90 top
R44 "49.9 Ohm" RESC1609X55X30NL10T20 3870,1400 r0 top
R45 "49.9 Ohm" RESC1609X55X30NL10T20 3745,1400 r180 top
R46 "49.9 Ohms" RESC1609X55X30NL10T20 3753.54,970 r180 top
R47 "49.9 Ohms" RESC1609X55X30NL10T20 3870,970 r180 top
RF1 "6-1879336-2" FP-CPF0603-MFG 2765,-380 r0 top
RF2 "6-1879336-2" FP-CPF0603-MFG 2910,-750 r270 top
RF3 "6-1879336-2" FP-CPF0603-MFG 2890,-335 r90 top
RF4 "6-1879336-2" FP-CPF0603-MFG 3090,-515 r0 top
RG1 "6-1879336-2" FP-CPF0603-MFG 2260,-620 r0 top
RG2 "6-1879336-2" FP-CPF0603-MFG 2260,-535 r180 top
RG3 "6-1879336-2" FP-CPF0603-MFG 2795,-775.77 r0 top
RG4 "6-1879336-2" FP-CPF0603-MFG 3035,-740 r90 top
RS1 "CRCW060350R0FKEA" FP-CRCW0603-e3-IPC_C 2120,-620 r0 top
RS2 "CRCW060350R0FKEA" FP-CRCW0603-e3-IPC_C 2120.77,-535 r180 top
RS3 "CRCW060350R0FKEA" FP-CRCW0603-e3-IPC_C 2845,-890 r90 top
RS4 "CRCW060350R0FKEA" FP-CRCW0603-e3-IPC_C 3125,-883.33 r90 top
RT1 "CR0603-FX-52R3ELF" FP-CR0603-IPC_A 2170,-747.56 r90 top
RT2 "CR0603-FX-52R3ELF" FP-CR0603-IPC_A 2170,-412.44 r270 top
RT3 "CR0603-FX-52R3ELF" FP-CR0603-IPC_A 2760,-895.77 r90 top
RT4 "CR0603-FX-52R3ELF" FP-CR0603-IPC_A 3035,-885 r90 top
U1 "LDL1117S33R" FP-SOT223-0046067-IPC_A 1288.82,-1418.13 r0 top
U2 "LDL1117S33R" FP-SOT223-0046067-IPC_A 2758.82,-1363.13 r0 top
U3 "LDL1117S33R" FP-SOT223-0046067-IPC_A 4343.82,-1388.13 r0 top
U4 "LDL1117S33R" FP-SOT223-0046067-IPC_A -49.69,-780 r90 top
U5 "LDL1117S33R" FP-SOT223-0046067-IPC_A 5340,-881.17 r90 top
U6 "LDL1117S33R" FP-SOT223-0046067-IPC_A 1300,1710 r0 top
U7 "LDL1117S33R" FP-SOT223-0046067-IPC_A 1300,1105 r0 top
U8 "AD5689RTCPZ-EP-RL7" FP-CP-16-22-IPC_C 1094.53,-515.25 r180 top
U9 "ADA4940" ADA4940-Footprint-1 2875.1,-590.16 r180 top
U10 "LTC1563-2CGN#PBF" LTC1563-2CGN#PBF-Footprint-1 2560,52.5 r0 top
U11 "LTC1563-2CGN#PBF" LTC1563-2CGN#PBF-Footprint-1 5143,57.5 r0 top
U12 "LTC1563-2CGN#PBF" LTC1563-2CGN#PBF-Footprint-1 3485,47.5 r0 top
U13 "LTC1563-2CGN#PBF" LTC1563-2CGN#PBF-Footprint-1 4305,52.5 r0 top

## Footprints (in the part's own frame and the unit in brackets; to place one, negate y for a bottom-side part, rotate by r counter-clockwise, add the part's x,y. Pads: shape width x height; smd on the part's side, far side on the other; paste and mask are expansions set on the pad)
61302011821 [mm] "Socket Header, Pitch 2.54 mm, THT, Vertical, single row, 20p"
  rrect50% 1.52x1.52 hole 1.02: 1(-24.13,0)
  round 1.52 hole 1.02: 2(-21.59,0) 3(-19.05,0) 4(-16.51,0) 5(-13.97,0) 6(-11.43,0) 7(-8.89,0) 8(-6.35,0) 9(-3.81,0) 10(-1.27,0) 11(1.27,0) 12(3.81,0) 13(6.35,0) 14(8.89,0) 15(11.43,0) 16(13.97,0) 17(16.51,0) 18(19.05,0) 19(21.59,0) 20(24.13,0)
  silkscreen extent -26.39,-1.35 25.78,1.35
ADA4940-Footprint-1 [mil]
  rect 10.81x31.68 smd paste+0 mask+0: 1(44.21,59.9) 2(24.53,59.9) 3(4.84,59.9) 4(-14.84,59.9) 5(-34.53,59.9) 6(-54.21,59.9) 13(-54.21,-89.9) 14(-34.53,-89.9) 15(-14.84,-89.9) 16(4.84,-89.9) 17(24.53,-89.9) 18(44.21,-89.9)
  rect 31.68x10.81 smd paste+0 mask+0: 7(-79.9,34.21) 8(-79.9,14.53) 9(-79.9,-5.16) 10(-79.9,-24.84) 11(-79.9,-44.53) 12(-79.9,-64.21) 19(69.9,-64.21) 20(69.9,-44.53) 21(69.9,-24.84) 22(69.9,-5.16) 23(69.9,14.53) 24(69.9,34.21)
  rect 104.33x104.33 smd paste+0 mask+0: HTAB(-5,-15)
  silkscreen extent -89,-99 79,69
ADI-CP-32-2_L [mm] "QFN, 32-Leads, Body 5x5mm, Pitch 0.5mm, Thermal Pad 3.1x3.1mm, IPC High Density"
  oval 0.8x0.25 smd: 1(-2.4,1.75) 2(-2.4,1.25) 3(-2.4,0.75) 4(-2.4,0.25) 5(-2.4,-0.25) 6(-2.4,-0.75) 7(-2.4,-1.25) 8(-2.4,-1.75) 17(2.4,-1.75) 18(2.4,-1.25) 19(2.4,-0.75) 20(2.4,-0.25) 21(2.4,0.25) 22(2.4,0.75) 23(2.4,1.25) 24(2.4,1.75)
  oval 0.25x0.8 smd: 9(-1.75,-2.4) 10(-1.25,-2.4) 11(-0.75,-2.4) 12(-0.25,-2.4) 13(0.25,-2.4) 14(0.75,-2.4) 15(1.25,-2.4) 16(1.75,-2.4) 25(1.75,2.4) 26(1.25,2.4) 27(0.75,2.4) 28(0.25,2.4) 29(-0.25,2.4) 30(-0.75,2.4) 31(-1.25,2.4) 32(-1.75,2.4)
  rect 3.1x3.1 smd: 33(0,0)
  silkscreen extent -3.47,-2.7 2.7,2.7
CAPC0603(1608)100_L [mm] "Chip Capacitor, Body 1.6x0.8mm, Height 1.0mm, IPC High Density"
  rect 0.7x0.9 smd: 1(-0.7,0) 2(0.7,0)
  silkscreen extent -0.05,-0.35 0.05,0.35
CAPC0603(1608)100_M [mm] "Chip Capacitor, Body 1.6x0.8mm, Height 1.0mm, IPC Low Density"
  rect 1.1x1.1 smd: 1(-0.9,0) 2(0.9,0)
  silkscreen extent -0.05,-0.45 0.05,0.45
CAPC0603(1608)100_N [mm] "Chip Capacitor, Body 1.6x0.8mm, Height 1.0mm, IPC Medium Density"
  rect 0.9x1 smd: 1(-0.8,0) 2(0.8,0)
  silkscreen extent -0.05,-0.4 0.05,0.4
CAPC1608X87X35LL15T15 [mm] "Chip Capacitor, 2-Leads, Body 1.60x0.80mm, IPC High Density"
  rect 0.8x0.9 smd: 1(-0.625,0) 2(0.625,0)
CAPC1608X90X35LL15T15 [mm] "Chip Capacitor, 2-Leads, Body 1.60x0.81mm, IPC High Density"
  rect 0.85x0.9 smd: 1(-0.65,0) 2(0.65,0)
CAPC1608X92X38LL15T08 [mm] "Chip Capacitor, 2-Leads, Body 1.60x0.80mm, IPC High Density"
  rect 0.75x0.9 smd: 1(-0.625,0) 2(0.625,0)
CAPC1608X92X38NL15T08 [mm] "Chip Capacitor, 2-Leads, Body 1.60x0.80mm, IPC Medium Density"
  rect 0.85x1 smd: 1(-0.675,0) 2(0.675,0)
CAPC1608X95X40LL15T15 [mm] "Chip Capacitor, 2-Leads, Body 1.60x0.80mm, IPC High Density"
  rect 0.85x0.9 smd: 1(-0.6,0) 2(0.6,0)
CAPC1608X95X40ML15T15 [mm] "Chip Capacitor, 2-Leads, Body 1.60x0.80mm, IPC Low Density"
  rect 1.05x1.1 smd: 1(-0.7,0) 2(0.7,0)
CAPC1608X95X40NL15T15 [mm] "Chip Capacitor, 2-Leads, Body 1.60x0.80mm, IPC Medium Density"
  rect 0.95x1 smd: 1(-0.65,0) 2(0.65,0)
CONN_SMA-J-P-H-RA-TH1_SAI [mil]
  round 83 / inner round 60 / far side round 83 hole 63 paste+0 mask+0: 1(0,0) 2(-100,100) 3(-100,-100) 4(100,-100) 5(100,100)
  silkscreen extent -143,-143 191,466
DEA142450BT3028A1 [mm]
  rect 0.25x0.325 smd: 1(-0.5,0) 2(0,-0.287) 3(0.5,-0.287) 4(0.5,0.288) 5(0,0.288)
  silkscreen extent -1.2,-0.05 -1.1,0.05
DLF0004A_MFG [mm] "Recommended Land Pattern"
  rrect15% 0.9x0.65 smd: 1(-0.75,0.825) 2(-0.75,-0.825) 3(0.75,-0.825) 4(0.75,0.825)
  silkscreen extent -1.87,-0.13 1.05,0.95
FP-BLM18-0_15-t0_8-IPC_B [mil]
  rect 43.55x37.73 smd paste+0 mask+0: 1(-26.62,0) 2(26.62,0)
  silkscreen extent -48,-35 48,35
FP-C0402C102K4RAC7411-MFG [mm]
  rect 0.52x0.52 smd paste+0 mask+0: 1(-0.4,0) 2(0.4,0)
  silkscreen extent -0.5,-0.63 0.5,0.64
FP-C1206C-EB-MFG [mm]
  rect 0.95x1.7 smd paste+0 mask+0: 1(-1.4,0) 2(1.4,0)
  silkscreen extent -0.55,-0.9 0.55,0.9
FP-C1608-080-0_1-IPC_C [mil]
  rect 36.66x31.97 smd paste+0 mask+0: 1(-21.28,0) 2(21.28,0)
  silkscreen extent -40,-33 40,33
FP-C2012-125-0_2-IPC_A [mil]
  rect 62.13x61.27 smd paste+0 mask+0: 1(-34.02,0) 2(34.02,0)
  silkscreen extent -65,-46 65,46
FP-CGA2B-IPC_B [mm]
  rect 0.372x0.572 smd paste+0 mask+0: 1(-0.55,0) 2(0.55,0)
  silkscreen extent -0.74,-0.69 0.74,0.69
FP-CGA2B-MFG [mm]
  rect 0.4x0.5 smd paste+0 mask+0: 1(-0.4,0) 2(0.4,0)
  silkscreen extent -0.53,-0.62 0.53,0.62
FP-CGA3E-0_3-0_1-IPC_A [mm]
  rect 0.956x1.206 smd paste+0 mask+0: 1(-1.025,0) 2(1.025,0)
  silkscreen extent -0.25,-0.6 0.25,0.6
FP-CGA5L-0_3-0_1-IPC_A [mm]
  rect 0.956x2.006 smd paste+0 mask+0: 1(-1.825,0) 2(1.825,0)
  silkscreen extent -1.05,-1 1.05,1
FP-CGA5L-MFG [mm]
  rect 1.1x1.35 smd paste+0 mask+0: 1(-1.65,0) 2(1.65,0)
  silkscreen extent -0.73,-0.9 0.73,0.9
FP-CP-16-22-IPC_C [mm]
  rect 0.731x0.239 smd paste+0 mask+0: 1(-1.391,0.75)
  rrect100% 0.731x0.239 smd paste+0 mask+0: 2(-1.391,0.25) 3(-1.391,-0.25) 4(-1.391,-0.75) 9(1.391,-0.75) 10(1.391,-0.25) 11(1.391,0.25) 12(1.391,0.75)
  rrect100% 0.239x0.731 smd paste+0 mask+0: 5(-0.75,-1.391) 6(-0.25,-1.391) 7(0.25,-1.391) 8(0.75,-1.391) 13(0.75,1.391) 14(0.25,1.391) 15(-0.25,1.391) 16(-0.75,1.391)
  rect 1.75x1.75 smd paste-1000 mask+0: 17(0,0)
  silkscreen extent -2.28,-1.5 1.5,1.5
FP-CPF0603-MFG [mm]
  rect 1x0.9 smd paste+0 mask+0: 1(-0.9,0) 2(0.9,0)
  silkscreen extent -0.83,-0.82 0.82,0.82
FP-CR0603-IPC_A [mil]
  rect 45.6x39.85 smd paste+0 mask+0: 1(-32.56,0) 2(32.56,0)
  silkscreen extent -55,-36 55,36
FP-CR0603-IPC_B [mil]
  rect 37.72x35.91 smd paste+0 mask+0: 1(-28.62,0) 2(28.62,0)
  silkscreen extent -47,-34 47,34
FP-CRCW0402-e3-IPC_C [mil]
  rect 18.43x18.6 smd paste+0 mask+0: 1(-15.83,0) 2(15.83,0)
  silkscreen extent -25,-27 25,27
FP-CRCW0603-e3-IPC_B [mil]
  rect 36.81x37.88 smd paste+0 mask+0: 1(-28.17,0) 2(28.17,0)
  silkscreen extent -30,-37 30,35
FP-CRCW0603-e3-IPC_C [mil]
  rect 28.94x33.94 smd paste+0 mask+0: 1(-24.23,0) 2(24.23,0)
  silkscreen extent -30,-33 30,33
FP-CRG0402-IPC_B [mil]
  rect 25.97x22.54 smd paste+0 mask+0: 1(-16.78,0) 2(16.78,0)
  silkscreen extent -30,-27 30,27
FP-CRGCQ0603-IPC_A [mil]
  rect 45.6x39.85 smd paste+0 mask+0: 1(-32.56,0) 2(32.56,0)
  silkscreen extent -55,-36 55,36
FP-CRGCQ0603-IPC_C [mil]
  rect 29.85x31.97 smd paste+0 mask+0: 1(-24.68,0) 2(24.68,0)
  silkscreen extent -40,-33 40,33
FP-DLW5BS-MFG [mil]
  round 34.99 smd paste+0 mask+0: 1(-37.16,-63.24) 4(-37.16,46.51)
  round 35.31 smd paste+0 mask+0: 2(38.63,-71.6) 3(38.63,71.6)
  silkscreen extent -136,-114 104,114
FP-GCJ21B-0_3-IPC_A [mil]
  rect 61.16x61.27 smd paste+0 mask+0: 1(-36.43,0) 2(36.43,0)
  silkscreen extent -67,-46 67,46
FP-GCM21B-0_15-IPC_A [mil]
  rect 55.34x59.38 smd paste+0 mask+0: 1(-36.47,0) 2(36.47,0)
  silkscreen extent -64,-45 64,45
FP-GCM155-0_05-IPC_A [mil]
  rect 28.16x26.48 smd paste+0 mask+0: 1(-18.84,0) 2(18.84,0)
  silkscreen extent -33,-29 33,29
FP-GQM187-0_15-IPC_C [mil]
  rect 31.75x33.79 smd paste+0 mask+0: 1(-24.64,0) 2(24.64,0)
  silkscreen extent -41,-34 41,34
FP-GRM31C-0_2-e0_3_0_8-IPC_B [mil]
  rect 53.33x71.11 smd paste+0 mask+0: 1(-54.16,0) 2(54.16,0)
  silkscreen extent -16,-36 16,36
FP-GRM188-0_1-e0_2_0_5-IPC_B [mil]
  rect 37.74x35.91 smd paste+0 mask+0: 1(-28.61,0) 2(28.61,0)
  silkscreen extent -47,-34 47,34
FP-LQG15HH_02-MFG [mm]
  rect 0.4x0.5 smd paste+0 mask+0: 1(-0.4,0) 2(0.4,0)
  silkscreen extent -1.27,-0.64 0.53,0.65
FP-LQG15WH_02-MFG [mm]
  rect 0.35x0.65 smd paste+0 mask+0: 1(-0.425,0) 2(0.425,0)
  silkscreen extent -1.28,-0.78 0.53,0.73
FP-LQW18CA_00-MFG [mm]
  rect 0.75x1 smd paste+0 mask+0: 1(-0.725,0) 2(0.725,0)
  silkscreen extent -0.87,-0.9 0.87,0.9
FP-MCT0603-IPC_B [mil]
  rect 34x37.88 smd paste+0 mask+0: 1(-28.72,0) 2(28.72,0)
  silkscreen extent -46,-35 46,35
FP-RK-3-MFG [mm]
  rect 0.86x1.27 smd paste+0 mask+0: 1(-1.5,-2.278) 3(1.5,-2.278)
  round 1.62 smd paste+0 mask+0: 2(0,0.164)
  silkscreen extent -2.3,-1.3 2.3,1.3
FP-RMCF0603-IPC_B [mil]
  rect 39.61x37.73 smd paste+0 mask+0: 1(-27.6,0) 2(27.6,0)
  silkscreen extent -47,-35 47,35
FP-RT0402-MFG [mm]
  rect 0.5x0.6 smd paste+0 mask+0: 1(-0.5,0) 2(0.5,0)
  silkscreen extent -0.5,-0.71 0.5,0.7
FP-SOT223-0046067-IPC_A [mm]
  rect 2.204x0.96 smd paste+0 mask+0: 1(-3.1,2.3)
  rrect100% 2.204x0.96 smd paste+0 mask+0: 2(-3.1,0) 3(-3.1,-2.3)
  rrect44% 2.204x3.26 smd paste+0 mask+0: 4(3.1,0)
  silkscreen extent -5.85,-3.25 1.75,3.25
FP-SR0603-MFG [mm]
  rect 0.9x0.8 smd paste+0 mask+0: 1(-0.85,0) 2(0.85,0)
  silkscreen extent -0.02,-0.45 0.02,0.45
FP-TSW-102-07-G-S-MFG [mm]
  rect 1.57x1.57 hole 1.02 paste+0 mask+0: 1(-1.27,0)
  round 1.57 hole 1.02 paste+0 mask+0: 2(1.27,0)
  silkscreen extent -3.42,-1.34 2.73,1.34
FP-TSW-102-07-L-S-MFG [mm]
  rect 1.57x1.57 hole 1.02 paste+0 mask+0: 1(-1.27,0)
  round 1.57 hole 1.02 paste+0 mask+0: 2(1.27,0)
  silkscreen extent -3.25,-1.34 2.73,1.34
FP-VJ0603Y105KXJCW1BC-MFG [mm]
  rect 0.8x0.8 smd paste+0 mask+0: 1(-0.75,0) 2(0.75,0)
  silkscreen extent -0.87,-0.78 0.87,0.78
LTC1563-2CGN#PBF-Footprint-1 [mil]
  rect 78x14 smd paste+0 mask+0: 1(-87,82.5) 2(-87,57.5) 3(-87,32.5) 4(-87,7.5) 5(-87,-17.5) 6(-87,-42.5) 7(-87,-67.5) 8(-87,-92.5) 9(107,-92.5) 10(107,-67.5) 11(107,-42.5) 12(107,-17.5) 13(107,7.5) 14(107,32.5) 15(107,57.5) 16(107,82.5)
  silkscreen extent -38,-108 58,98
QFN50P400X400X100-25N-D [mm]
  rect 0.85x0.3 smd: 1(-1.95,1.25) 2(-1.95,0.75) 3(-1.95,0.25) 4(-1.95,-0.25) 5(-1.95,-0.75) 6(-1.95,-1.25) 13(1.95,-1.25) 14(1.95,-0.75) 15(1.95,-0.25) 16(1.95,0.25) 17(1.95,0.75) 18(1.95,1.25)
  rect 0.3x0.85 smd: 7(-1.25,-1.95) 8(-0.75,-1.95) 9(-0.25,-1.95) 10(0.25,-1.95) 11(0.75,-1.95) 12(1.25,-1.95) 19(1.25,1.95) 20(0.75,1.95) 21(0.25,1.95) 22(-0.25,1.95) 23(-0.75,1.95) 24(-1.25,1.95)
  rect 2.55x2.55 smd: 25(0,0)
  silkscreen extent -2.5,1.88 -2.25,2.12
RESC1609X50X30LL10T20 [mm] "Chip Resistor, 2-Leads, Body 1.55x0.85mm, IPC High Density"
  rect 0.7x0.85 smd: 1(-0.575,0) 2(0.575,0)
RESC1609X50X30NL10T20 [mm] "Chip Resistor, 2-Leads, Body 1.55x0.85mm, IPC Medium Density"
  rect 0.8x0.95 smd: 1(-0.625,0) 2(0.625,0)
RESC1609X55X30NL10T20 [mm] "Chip Resistor, 2-Leads, Body 1.60x0.85mm, IPC Medium Density"
  rect 0.95x0.95 smd: 1(-0.725,0) 2(0.725,0)
SMTC-TSW-106-07-S-S_V [mm] "Header, 6-Leads, Body 15.24x2.54mm, Pitch 2.54mm"
  rect 1.55x1.55 hole 1.02: 1(-6.35,0)
  round 1.55 hole 1.02: 2(-3.81,0) 3(-1.27,0) 4(1.27,0) 5(3.81,0) 6(6.35,0)
  silkscreen extent -7.62,-1.27 7.62,2.04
